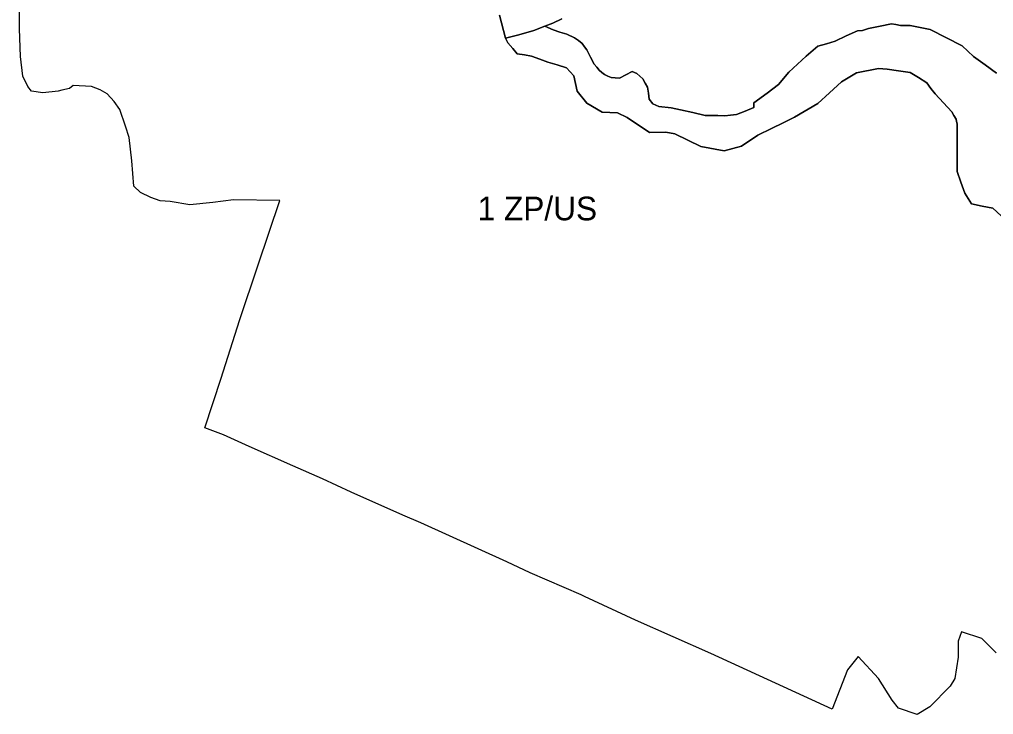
# Model space of a CAD drawing. Extents: x 7423432 to 7425824, y 5537848 to 5539677.
# Drawn here: x 7423465.5 to 7423877.3, y 5538126.8 to 5538420.5 of the extents above; entities that cross this region are included whole.
import ezdxf

# ---------------------------------------------------------------- set-up
doc = ezdxf.new("R2010")
doc.units = 0
doc.layers.add('linie_rozgraniczajace', color=7, linetype='Continuous')
doc.layers.add('oznaczenia_przeznaczen', color=7, linetype='Continuous')

msp = doc.modelspace()

# ---------------------------------------------------------------- linework, layer by layer
at = {"layer": 'linie_rozgraniczajace'}
for points in [[(7423555.97, 5538344.22), (7423547.23, 5538343.15), (7423537.61, 5538342.16), (7423529.29, 5538343.53), (7423525, 5538343.79), (7423521.01, 5538345.22), (7423516.75, 5538347.42), (7423513.83, 5538350.12), (7423512.96, 5538360.75), (7423511.88, 5538370.66), (7423510.32, 5538375.34), (7423507.99, 5538382.42), (7423505.56, 5538385.89), (7423502.63, 5538389.04), (7423499.64, 5538390.8), (7423495.98, 5538392.13), (7423488.22, 5538392.58), (7423486.69, 5538391.31), (7423483.39, 5538390.58), (7423481.85, 5538390.23), (7423475.39, 5538389.46), (7423470.58, 5538390.21), (7423469.04, 5538392.1), (7423466.88, 5538396.51), (7423465.96, 5538404.88), (7423465.53, 5538416.46), (7423465.55, 5538430.05)], [(7423668.53, 5538422.35), (7423670.97, 5538412.61), (7423672, 5538410.64), (7423674.12, 5538408.15), (7423675.97, 5538405.98), (7423678.99, 5538405.5), (7423682, 5538405.01), (7423685.47, 5538403.7), (7423688.93, 5538402.39), (7423692.87, 5538401.25), (7423696.8, 5538400.11), (7423699.94, 5538396.71), (7423701.32, 5538390.17), (7423705.41, 5538385.12), (7423711.81, 5538381.27), (7423718.41, 5538380.99), (7423722.38, 5538379.09), (7423731.85, 5538372.76), (7423738.82, 5538372.92), (7423742.66, 5538372.16), (7423753.6, 5538366.8), (7423763.52, 5538364.95), (7423770.84, 5538366.98), (7423777.64, 5538371.64), (7423783.53, 5538374.44), (7423788.38, 5538376.8), (7423793.22, 5538379.17), (7423803.05, 5538384.94), (7423808.05, 5538389.55), (7423813.05, 5538394.16), (7423819.41, 5538397.97), (7423828.74, 5538399.79), (7423832.3, 5538399.51), (7423837.18, 5538398.82), (7423842.06, 5538398.14), (7423845.57, 5538395.91), (7423849.08, 5538393.67), (7423850.85, 5538391.37), (7423852.62, 5538389.06), (7423856.16, 5538385.24), (7423859.69, 5538381.42), (7423860.59, 5538379.92), (7423861.5, 5538378.43), (7423861.73, 5538377.42), (7423861.96, 5538376.42), (7423861.96, 5538366.34)], [(7423694.76, 5538420.74), (7423691.06, 5538418.99), (7423687.58, 5538417.61), (7423682.97, 5538415.78), (7423679.54, 5538414.84), (7423676.11, 5538413.89), (7423670.97, 5538412.61), (7423668.53, 5538422.35)], [(7423670.97, 5538412.61), (7423676.11, 5538413.89), (7423679.54, 5538414.84), (7423682.97, 5538415.78), (7423687.58, 5538417.61), (7423691.12, 5538416.06), (7423694.02, 5538415.15), (7423696.91, 5538414.24), (7423700.17, 5538412.77), (7423701.81, 5538411.55), (7423703.46, 5538410.33), (7423704.45, 5538408.98), (7423705.44, 5538407.64), (7423706.98, 5538404.6), (7423708.52, 5538401.57), (7423709.58, 5538400.33), (7423710.64, 5538399.1), (7423711.76, 5538398.14), (7423712.89, 5538397.18), (7423714.26, 5538396.56), (7423715.63, 5538395.93), (7423717.41, 5538395.77), (7423719.19, 5538395.62), (7423721.89, 5538397.03), (7423724.58, 5538398.44), (7423725.59, 5538398.06), (7423726.59, 5538397.69), (7423727.8, 5538396.53), (7423729.02, 5538395.37), (7423730.02, 5538393.61), (7423731.03, 5538391.85), (7423731.41, 5538389.33), (7423731.79, 5538386.81), (7423733.25, 5538384.83), (7423735.9, 5538383.75), (7423740.99, 5538383.13), (7423744.96, 5538382.35), (7423750.17, 5538381.11), (7423755.37, 5538379.86), (7423758.06, 5538379.89), (7423760.75, 5538379.91), (7423763.71, 5538379.81), (7423766.16, 5538380.06), (7423768.61, 5538380.32), (7423772.33, 5538381.81), (7423776.04, 5538383.29), (7423775.99, 5538385.24), (7423781.64, 5538389.3), (7423786.47, 5538393.07), (7423790.8, 5538398.19), (7423794.43, 5538401.58), (7423798.06, 5538404.96), (7423803.06, 5538409.18), (7423806.71, 5538410.23), (7423810.36, 5538411.28), (7423815.07, 5538413.51), (7423819.78, 5538415.74), (7423821.89, 5538415.83), (7423824.53, 5538416.66), (7423829.35, 5538417.63), (7423834.17, 5538418.6), (7423836.08, 5538418.3), (7423838, 5538417.99), (7423842.07, 5538417.9), (7423850.61, 5538416.19), (7423864.09, 5538409.3), (7423868.83, 5538404.86), (7423873.83, 5538401.26), (7423878.57, 5538397.86)], [(7423687.58, 5538417.61), (7423691.06, 5538418.99), (7423694.76, 5538420.74)], [(7423878.57, 5538397.86), (7423873.83, 5538401.26), (7423868.83, 5538404.86), (7423864.09, 5538409.3), (7423850.61, 5538416.19), (7423842.07, 5538417.9), (7423838, 5538417.99), (7423836.08, 5538418.3), (7423834.17, 5538418.6), (7423829.35, 5538417.63), (7423824.53, 5538416.66), (7423821.89, 5538415.83), (7423819.78, 5538415.74), (7423815.07, 5538413.51), (7423810.36, 5538411.28), (7423806.71, 5538410.23), (7423803.06, 5538409.18), (7423798.06, 5538404.96), (7423794.43, 5538401.58), (7423790.8, 5538398.19), (7423786.47, 5538393.07), (7423781.64, 5538389.3), (7423775.99, 5538385.24), (7423776.04, 5538383.29), (7423772.33, 5538381.81), (7423768.61, 5538380.32), (7423766.16, 5538380.06), (7423763.71, 5538379.81), (7423760.75, 5538379.91), (7423758.06, 5538379.89), (7423755.37, 5538379.86), (7423750.17, 5538381.11), (7423744.96, 5538382.35), (7423740.99, 5538383.13), (7423735.9, 5538383.75), (7423733.25, 5538384.83), (7423731.79, 5538386.81), (7423731.41, 5538389.33), (7423731.03, 5538391.85), (7423730.02, 5538393.61), (7423729.02, 5538395.37), (7423727.8, 5538396.53), (7423726.59, 5538397.69), (7423725.59, 5538398.06), (7423724.58, 5538398.44), (7423721.89, 5538397.03), (7423719.19, 5538395.62), (7423717.41, 5538395.77), (7423715.63, 5538395.93), (7423714.26, 5538396.56), (7423712.89, 5538397.18), (7423711.76, 5538398.14), (7423710.64, 5538399.1), (7423709.58, 5538400.33), (7423708.52, 5538401.57), (7423706.98, 5538404.6), (7423705.44, 5538407.64), (7423704.45, 5538408.98), (7423703.46, 5538410.33), (7423701.81, 5538411.55), (7423700.17, 5538412.77), (7423696.91, 5538414.24), (7423694.02, 5538415.15), (7423691.12, 5538416.06), (7423687.58, 5538417.61)], [(7423861.96, 5538376.42), (7423861.73, 5538377.42), (7423861.5, 5538378.43), (7423860.59, 5538379.92), (7423859.69, 5538381.42), (7423856.16, 5538385.24), (7423852.62, 5538389.06), (7423850.85, 5538391.37), (7423849.08, 5538393.67), (7423845.57, 5538395.91), (7423842.06, 5538398.14), (7423837.18, 5538398.82), (7423832.3, 5538399.51), (7423828.74, 5538399.79), (7423819.41, 5538397.97), (7423813.05, 5538394.16), (7423808.05, 5538389.55), (7423803.05, 5538384.94), (7423793.22, 5538379.17), (7423788.38, 5538376.8), (7423783.53, 5538374.44), (7423777.64, 5538371.64), (7423770.84, 5538366.98), (7423763.52, 5538364.95), (7423753.6, 5538366.8), (7423742.66, 5538372.16), (7423738.82, 5538372.92), (7423731.85, 5538372.76), (7423722.38, 5538379.09), (7423718.41, 5538380.99), (7423711.81, 5538381.27), (7423705.41, 5538385.12), (7423701.32, 5538390.17), (7423699.94, 5538396.71), (7423696.8, 5538400.11), (7423692.87, 5538401.25), (7423688.93, 5538402.39), (7423685.47, 5538403.7), (7423682, 5538405.01), (7423678.99, 5538405.5), (7423675.97, 5538405.98), (7423674.12, 5538408.15), (7423672, 5538410.64), (7423670.97, 5538412.61)], [(7423880.57, 5538337.47), (7423877.01, 5538340.77), (7423872.55, 5538341.65), (7423868.09, 5538342.53), (7423866.62, 5538344.82), (7423865.15, 5538347.12), (7423863.56, 5538351.69), (7423861.96, 5538356.27), (7423861.96, 5538366.34), (7423861.96, 5538376.42)], [(7423861.96, 5538366.34), (7423861.96, 5538356.27), (7423863.56, 5538351.69), (7423865.15, 5538347.12), (7423866.62, 5538344.82), (7423868.09, 5538342.53), (7423872.55, 5538341.65), (7423877.01, 5538340.77), (7423880.57, 5538337.47)], [(7423878.5, 5538152.86), (7423877.33, 5538153.99), (7423872.44, 5538158.9), (7423863.76, 5538161.7), (7423862.39, 5538157.75), (7423862.35, 5538150.99), (7423861.02, 5538142), (7423858.94, 5538138.81), (7423850.37, 5538130.01), (7423845, 5538126.82), (7423837.22, 5538129.53), (7423834.5, 5538132.88), (7423828.76, 5538142.05), (7423820.04, 5538151.39), (7423815.57, 5538145.66), (7423809.16, 5538129.12), (7423757.78, 5538152.56), (7423726.02, 5538166.75), (7423704.45, 5538176.74), (7423703.01, 5538177.4), (7423681.49, 5538186.66), (7423671.54, 5538191.32), (7423635.16, 5538207.76), (7423627.59, 5538210.99), (7423605.7, 5538220.78), (7423593.61, 5538226.38), (7423581.04, 5538231.85), (7423562.59, 5538240.07), (7423551.72, 5538244.92), (7423543.95, 5538248.01), (7423550.82, 5538268.91), (7423558.58, 5538293.26), (7423566.48, 5538316.75), (7423575.55, 5538343.98), (7423555.97, 5538344.22)]]:
    msp.add_lwpolyline(points, dxfattribs=at)

# ---------------------------------------------------------------- texts
at = {"layer": 'oznaczenia_przeznaczen'}
msp.add_text('1 ZP/US', height=10, dxfattribs=at).set_placement((7423659.19, 5538335.62))

doc.saveas('drawing.dxf')
